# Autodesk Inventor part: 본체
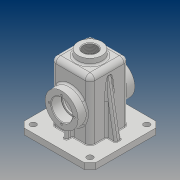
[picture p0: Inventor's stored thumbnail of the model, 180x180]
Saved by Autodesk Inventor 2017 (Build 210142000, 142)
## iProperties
Part Number: 본체
Material: 일반
Document SubType Name: Modeling
Designer: 20
Density: 1 g/cm^3
Appearance: 기본값
Author: 20
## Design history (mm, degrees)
sketch "스케치1"
  geometry: L1 (-32.5, -32.5)-(32.5, -32.5); L2 (32.5, -32.5)-(32.5, 32.5); L3 (32.5, 32.5)-(-32.5, 32.5); L4 (-32.5, 32.5)-(-32.5, -32.5); L5 (-32.5, -32.5)-(32.5, 32.5); L6 (32.5, -32.5)-(-32.5, 32.5); 1 further point
  constraints: 12 end point, 2 midpoint, 2 parallel, 1 horizontal, 1 perpendicular
  dimensions: "d0" = 65 distance of L2.end L3.end; "d1" = 65 distance of L1.end L2.end
extrude "돌출1" new body sketch "스케치1" distance "d2" = 110; taper "d3" = 0 deg
fillet "모깎기1" dims "d4" = 8
fillet "모깎기2" dims "d5" = 8
feature "쉘1" dims "d6" = 5
sketch "스케치2"
  geometry: L1 (60, 60)-(-60, 60); L2 (-60, 60)-(-60, -60); L3 (-60, -60)-(60, -60); L4 (60, -60)-(60, 60); L5 (60, 60)-(-60, -60); L6 (-60, 60)-(60, -60); L7 (24.5, -27.5)-(-24.5, -27.5) reference; L8 (-27.5, -24.5)-(-27.5, 24.5) reference; L9 (-24.5, 27.5)-(24.5, 27.5) reference; L10 (27.5, 24.5)-(27.5, -24.5) reference; A1 r 3 centre (-24.5, -24.5) between (-27.5, -24.5) and (-24.5, -27.5) reference; A2 r 3 centre (-24.5, 24.5) between (-24.5, 27.5) and (-27.5, 24.5) reference; A3 r 3 centre (24.5, 24.5) between (27.5, 24.5) and (24.5, 27.5) reference; A4 r 3 centre (24.5, -24.5) between (24.5, -27.5) and (27.5, -24.5) reference; 1 further point
  constraints: 12 end point, 2 midpoint, 2 parallel, 1 horizontal, 1 perpendicular
  dimensions: "d7" = 120 distance of L2.end L3.end; "d8" = 120 distance of L1.end L2.end
extrude "돌출2" join sketch "스케치2" distance "d9" = 10; taper "d10" = 0 deg
chamfer "모따기1" distance "d11" = 10; stored, may be unused: second distance "d12" = 2, angle "d13" = 45 deg
sketch "스케치3"
  geometry: L1 (74.5, -102)-(-25.5, -102) reference; C1 r 27.5 at (24.5, -47); 2 further points
  constraints: 1 centre point, 1 midpoint, 1 vertical alignment
  dimensions: "d14" = 55 diameter of C1; "d15" = 55 distance from line of L1 C1.centre
extrude "돌출3" join sketch "스케치3" distance "d16" = 15; taper "d17" = 0 deg
sketch "스케치4"
  geometry: L1 (-24.5, -27.5)-(24.5, -27.5) reference; L2 (-3, -27.5)-(3, -27.5); L3 (3, -27.5)-(3, -42.5); L4 (3, -42.5)-(-3, -42.5); L5 (-3, -42.5)-(-3, -27.5); 2 further points
  constraints: 8 end point, 2 parallel, 1 horizontal, 1 midpoint, 1 perpendicular, 1 point on line, 1 vertical alignment
  dimensions: "d18" = 6 distance of L3.end L4.end; "d19" = 15 distance between parallel lines of L1 L4
extrude "돌출4" join sketch "스케치4" stored distance "d20" = 15; taper "d21" = 0 deg
sketch "스케치5"
  geometry: L1 (-32.5, 102)-(-32.5, 10) reference; L2 (-32.5, 97.905)-(-48, 10); L3 (-60, 10)-(-60, 0) reference; L4 (-50, 10)-(-60, 10) reference; 1 further point
  constraints: 2 end point, 2 point on line
  dimensions: "d22" = 12 distance from line of L2.end L3; "d23" = 10 deg angle of L3 L2
feature "리브1" sketch "스케치5" dims "d24" = 1, "d25" = 10, "d26" = 0, "d27" = 0, "d28" = 1, "d29" = 1
sketch "스케치6"
  geometry: C1 r 15 at (0, 0); C2 r 27.5 at (0, 0) reference; 1 further point
  constraints: 1 centre point, 1 concentric
  dimensions: "d30" = 30 diameter of C1
extrude "돌출5" cut sketch "스케치6" distance "d31" = 128.75; taper "d32" = 0 deg
sketch "스케치7"
  geometry: C1 r 15 at (0, 0) reference; C2 r 17.5 at (0, 0); 1 further point
  constraints: 1 centre point, 1 coincident
  dimensions: "d33" = 35 diameter of C2
extrude "돌출6" cut sketch "스케치7" distance "d34" = 17; taper "d35" = 0 deg
sketch "스케치8"
  geometry: C1 r 20 at (0, 0); 1 further point
  constraints: 1 centre point, 1 coincident
  dimensions: "d36" = 40 diameter of C1
extrude "돌출7" join sketch "스케치8" distance "d37" = 10; taper "d38" = 0 deg
hole "구멍1" diameter "d41" = 22.835; stored, may be unused: countersink angle "d45" = 90 deg, drill point angle "d47" = 118 deg; dims "d39" = 10, "d40" = 10, "d42" = 50, "d43" = 4, "d44" = 2, "d46" = 30
sketch "스케치9" dims "d48" = 42
  geometry: C1 r 27.5 at (0, 0) reference; 3 further points
  constraints: 2 vertical alignment, 3 other
hole "구멍2" sketch "스케치9" at (0, 21) diameter "d49" = 3.242; stored, may be unused: countersink angle "d53" = 90 deg, drill point angle "d55" = 118 deg; dims "d50" = 8, "d51" = 4, "d52" = 2, "d54" = 10
sketch "스케치10"
  geometry: L1 (0, 0)-(0, 109.114); L2 (0, 0)-(-97.13, 0); C1 r 5 at (-47.5, 47.5)
  constraints: 4 end point, 1 centre point, 1 horizontal, 1 vertical
  dimensions: "d59" = 10 diameter of C1; "d62" = 47.5 distance from line of L1 C1.centre; "d63" = 47.5 distance from line of C1.centre L2
extrude "돌출8" cut sketch "스케치10" distance "d64" = 20.5; taper "d65" = 0 deg
feature "면 기울기1" dims angle "d72" = 5 deg
fillet "모깎기3" dims "d73" = 0.3
chamfer "모따기2" distance "d74" = 1; stored, may be unused: second distance "d75" = 2, angle "d76" = 45 deg
fillet "모깎기4" dims "d77" = 3
fillet "모깎기5" dims "d78" = 3
fillet "모깎기6" dims "d79" = 3
fillet "모깎기7" dims "d80" = 3
fillet "모깎기8" dims "d81" = 1
fillet "모깎기9" dims "d82" = 3
fillet "모깎기10" dims "d83" = 3
node "작업 평면1"
sketch "스케치11"
  geometry: L1 (20, 120)-(-20, 120) reference; L2 (-32.5, 102)-(-32.5, 11) reference; 2 further points
  constraints: 1 other
  dimensions: "d85" = 26 distance from line of L1 point (0, 94); "d86" = 32.5 distance from line of point (0, 94) L2
feature "엠보싱1" sketch "스케치11" dims "d87" = 0.5, "d88" = 0
node "솔리드1"
mirror "미러1"
mirror "미러2"
mirror "미러3"
pattern_circular "원형 패턴1" dims angle "d57" = 360 deg
mirror "미러4"
pattern_linear "직사각형 패턴1" dims "d68" = 95, "d71" = 95
